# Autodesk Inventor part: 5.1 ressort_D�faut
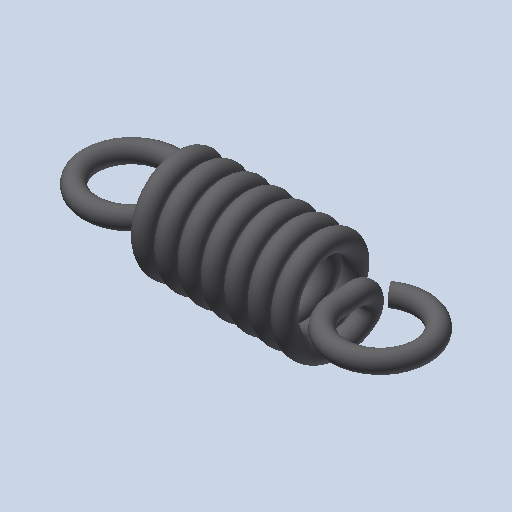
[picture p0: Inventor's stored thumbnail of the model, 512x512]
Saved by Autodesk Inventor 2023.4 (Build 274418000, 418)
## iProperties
Created: 2011-01
Part Number: 5.1 ressort_D�faut
Document SubType Name: Modeling
Designer: eric
Density: 1 g/cm^3
Mass: 3.95849 g
Surface Area: 45.6258 cm^2
Volume: 3.95849 cm^3
Material: Générique
Appearance: Red
Author: eric
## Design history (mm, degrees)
feature "Base1"
node "Corps solides"
node "Corps surfaciques"
node "Solide1"
